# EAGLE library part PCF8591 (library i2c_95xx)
8-Bit A/D and D/A Converter
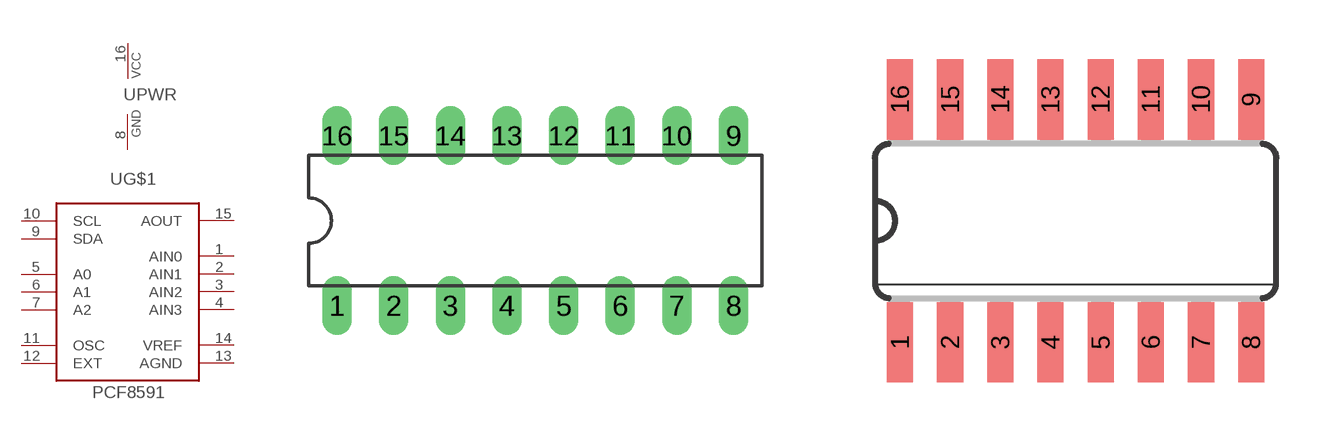
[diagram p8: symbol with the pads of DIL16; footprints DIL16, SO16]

Designator prefix -; gates PWR=PWRN G$1=PCF8591

## PCF8591P  [DIL16]
1  G$1:AIN0  in
2  G$1:AIN1  in
3  G$1:AIN2  in
4  G$1:AIN3  in
5  G$1:A0  in
6  G$1:A1  in
7  G$1:A2  in
8  PWR:GND  pwr
9  G$1:SDA
10  G$1:SCL  in
11  G$1:OSC
12  G$1:EXT  in
13  G$1:AGND
14  G$1:VREF  in
15  G$1:AOUT  out
16  PWR:VCC  pwr

## PCF8591T  [SO16]
Pads as for DIL16

## Footprint DIL16 (pad centres in mm)
drill 0.813 long: 1 -8.89,-3.81; 2 -6.35,-3.81; 3 -3.81,-3.81; 4 -1.27,-3.81; 5 1.27,-3.81; 6 3.81,-3.81; 7 6.35,-3.81; 8 8.89,-3.81; 9 8.89,3.81; 10 6.35,3.81; 11 3.81,3.81; 12 1.27,3.81; 13 -1.27,3.81; 14 -3.81,3.81; 15 -6.35,3.81; 16 -8.89,3.81

## Footprint SO16 (pad centres in mm)
smd 0.66 x 2.032: 1 -4.445,-3.073; 2 -3.175,-3.073; 3 -1.905,-3.073; 4 -0.635,-3.073; 5 0.635,-3.073; 6 1.905,-3.073; 7 3.175,-3.073; 8 4.445,-3.073; 9 4.445,3.073; 10 3.175,3.073; 11 1.905,3.073; 12 0.635,3.073; 13 -0.635,3.073; 14 -1.905,3.073; 15 -3.175,3.073; 16 -4.445,3.073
